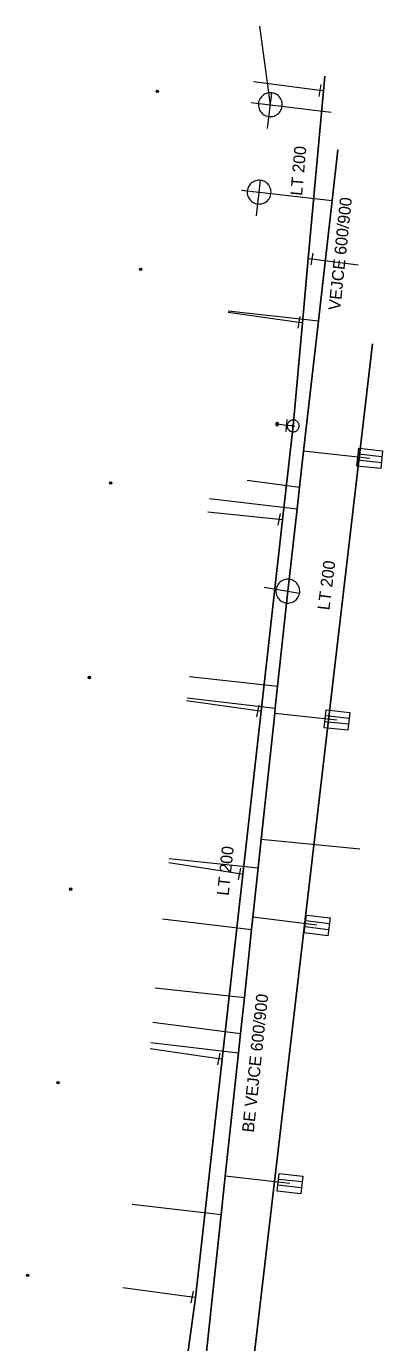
# Model space of a CAD drawing. Extents: x -783064 to -782702, y -1007904 to -1007145.
# Drawn here: x -782796 to -782766.2, y -1007400.8 to -1007290.3 of the extents above; entities that cross this region are included whole.
import ezdxf

# ---------------------------------------------------------------- set-up
doc = ezdxf.new("R2010")
doc.units = 0
doc.header["$LTSCALE"] = 0.4
doc.header["$PDMODE"] = 32
doc.header["$PDSIZE"] = 0.2
for name, color, linetype, lineweight in [('1', 7, 'Continuous', 13), ('11', 7, 'Continuous', 13), ('13', 7, 'Continuous', 13), ('14', 7, 'Continuous', 13), ('17', 7, 'Continuous', 25), ('22', 7, 'Continuous', 13), ('34', 7, 'Continuous', 13), ('47', 7, 'Continuous', 13), ('9', 7, 'Continuous', 13)]:
    doc.layers.add(name, color=color, linetype=linetype, lineweight=lineweight)

msp = doc.modelspace()

# ---------------------------------------------------------------- linework, layer by layer
at = {"layer": '1'}
for p in [(-782785.07, -1007295.79), (-782786.46, -1007310.729), (-782788.969, -1007328.649), (-782790.76, -1007344.969), (-782792.32, -1007362.729), (-782793.39, -1007378.959), (-782795.94, -1007395.139)]:
    msp.add_point(p, dxfattribs=at)
at = {"layer": '11'}
for p, q in [((-782776.496, -1007290.33), (-782775.599, -1007296.909)), ((-782777.204, -1007296.714), (-782775.599, -1007296.909)), ((-782775.599, -1007296.909), (-782770.506, -1007297.528)), ((-782778.017, -1007304.068), (-782776.537, -1007304.241)), ((-782776.537, -1007304.241), (-782770.429, -1007304.956)), ((-782779.125, -1007314.215), (-782771.569, -1007315.044)), ((-782767.274, -1007326.579), (-782772.805, -1007325.976)), ((-782777.54, -1007328.416), (-782773.146, -1007328.99)), ((-782780.703, -1007329.958), (-782773.35, -1007330.802)), ((-782782.381, -1007344.886), (-782774.984, -1007345.702)), ((-782782.58, -1007346.681), (-782775.18, -1007347.535)), ((-782770.021, -1007348.535), (-782775.227, -1007347.977)), ((-782768.104, -1007359.371), (-782776.357, -1007358.573)), ((-782784.073, -1007360.146), (-782776.611, -1007360.948)), ((-782771.688, -1007365.759), (-782777.052, -1007365.088)), ((-782784.626, -1007365.221), (-782777.162, -1007366.117)), ((-782785.256, -1007371.004), (-782777.771, -1007371.826)), ((-782785.437, -1007373.877), (-782778.092, -1007374.836)), ((-782785.601, -1007375.589), (-782778.267, -1007376.47)), ((-782773.95, -1007387.429), (-782779.371, -1007386.822)), ((-782787.188, -1007389.165), (-782779.714, -1007390.038))]:
    msp.add_line(p, q, dxfattribs=at)
at = {"layer": '13'}
for p, q in [((-782771.453, -1007295.717), (-782777.014, -1007294.994)), ((-782772.123, -1007309.847), (-782768.225, -1007310.354)), ((-782773.205, -1007315.178), (-782779.139, -1007314.338)), ((-782774.865, -1007331.708), (-782780.827, -1007331.085)), ((-782776.662, -1007347.776), (-782782.629, -1007346.914)), ((-782778.192, -1007361.449), (-782784.114, -1007360.525)), ((-782779.928, -1007376.969), (-782785.661, -1007376.137)), ((-782782.164, -1007396.953), (-782787.97, -1007396.189))]:
    msp.add_line(p, q, dxfattribs=at)
at = {"layer": '14'}
for p, q in [((-782771.154, -1007295.742), (-782771.453, -1007295.717)), ((-782772.421, -1007309.814), (-782772.123, -1007309.847)), ((-782772.907, -1007315.211), (-782773.205, -1007315.178)), ((-782774.256, -1007323.821), (-782775.023, -1007323.703)), ((-782773.685, -1007323.861), (-782774.256, -1007323.821)), ((-782774.568, -1007331.749), (-782774.865, -1007331.708)), ((-782776.364, -1007347.807), (-782776.662, -1007347.776)), ((-782777.895, -1007361.492), (-782778.192, -1007361.449)), ((-782779.629, -1007376.989), (-782779.928, -1007376.969)), ((-782781.868, -1007397.002), (-782782.164, -1007396.953))]:
    msp.add_line(p, q, dxfattribs=at)
at = {"layer": '14', "lineweight": 25}
for points in [[(-782774.133, -1007337.723), (-782773.35, -1007330.802), (-782773.146, -1007328.99), (-782772.805, -1007325.976), (-782771.569, -1007315.044), (-782770.429, -1007304.956), (-782769.945, -1007300.681)], [(-782782.09, -1007412.3), (-782779.714, -1007390.038), (-782779.371, -1007386.822), (-782778.267, -1007376.47), (-782778.092, -1007374.836), (-782777.771, -1007371.826), (-782777.162, -1007366.117), (-782777.052, -1007365.088), (-782776.611, -1007360.948), (-782776.357, -1007358.573), (-782775.227, -1007347.977), (-782775.18, -1007347.535), (-782774.984, -1007345.702), (-782774.133, -1007337.723)]]:
    msp.add_lwpolyline(points, dxfattribs=at)
at = {"layer": '17'}
msp.add_line((-782777.911, -1007410.054), (-782767.049, -1007316.969), dxfattribs=at)
for points in [[(-782773.685, -1007323.861), (-782772.907, -1007315.211), (-782772.421, -1007309.814), (-782771.154, -1007295.742), (-782771.043, -1007294.509)], [(-782782.979, -1007405.1), (-782781.87, -1007397.02), (-782779.629, -1007376.989), (-782777.895, -1007361.492), (-782776.364, -1007347.807), (-782774.568, -1007331.749), (-782773.685, -1007323.861)]]:
    msp.add_lwpolyline(points, dxfattribs=at)
at = {"layer": '22'}
for p, q in [((-782775.84, -1007298.894), (-782775.478, -1007295.916)), ((-782776.769, -1007306.227), (-782776.42, -1007303.248)), ((-782766.242, -1007326.446), (-782768.23, -1007326.229)), ((-782766.296, -1007326.943), (-782768.284, -1007326.726)), ((-782776.103, -1007337.375), (-782773.148, -1007337.896)), ((-782768.989, -1007348.4), (-782770.978, -1007348.187)), ((-782769.043, -1007348.897), (-782771.031, -1007348.684)), ((-782770.716, -1007366.139), (-782772.701, -1007365.89)), ((-782770.654, -1007365.642), (-782772.639, -1007365.394)), ((-782772.918, -1007387.299), (-782774.905, -1007387.077)), ((-782772.973, -1007387.796), (-782774.961, -1007387.573))]:
    msp.add_line(p, q, dxfattribs=at)
for points in [[(-782774.606, -1007297.03), (-782774.599, -1007296.921), (-782774.604, -1007296.811), (-782774.62, -1007296.703), (-782774.648, -1007296.597), (-782774.688, -1007296.495), (-782774.739, -1007296.398), (-782774.8, -1007296.307), (-782774.871, -1007296.224), (-782774.95, -1007296.148), (-782775.037, -1007296.082), (-782775.13, -1007296.025), (-782775.231, -1007295.98), (-782775.334, -1007295.945), (-782775.441, -1007295.922), (-782775.551, -1007295.91), (-782775.66, -1007295.911), (-782775.769, -1007295.923), (-782775.876, -1007295.948), (-782775.979, -1007295.984), (-782776.077, -1007296.031), (-782776.171, -1007296.089), (-782776.257, -1007296.156), (-782776.335, -1007296.233), (-782776.405, -1007296.317), (-782776.465, -1007296.409), (-782776.514, -1007296.507), (-782776.552, -1007296.61), (-782776.579, -1007296.715), (-782776.595, -1007296.824), (-782776.598, -1007296.934), (-782776.59, -1007297.042), (-782776.569, -1007297.15), (-782776.537, -1007297.254), (-782776.494, -1007297.355), (-782776.439, -1007297.451), (-782776.375, -1007297.539), (-782776.302, -1007297.62), (-782776.22, -1007297.693), (-782776.131, -1007297.756), (-782776.034, -1007297.809), (-782775.934, -1007297.851), (-782775.829, -1007297.882), (-782775.72, -1007297.902), (-782775.611, -1007297.909), (-782775.502, -1007297.904), (-782775.394, -1007297.888), (-782775.288, -1007297.859), (-782775.185, -1007297.82), (-782775.089, -1007297.769), (-782774.998, -1007297.708), (-782774.914, -1007297.638), (-782774.838, -1007297.558), (-782774.771, -1007297.472), (-782774.716, -1007297.378), (-782774.669, -1007297.279), (-782774.635, -1007297.174), (-782774.611, -1007297.067)], [(-782775.543, -1007304.357), (-782775.537, -1007304.248), (-782775.542, -1007304.139), (-782775.559, -1007304.03), (-782775.587, -1007303.925), (-782775.628, -1007303.823), (-782775.679, -1007303.726), (-782775.741, -1007303.635), (-782775.812, -1007303.553), (-782775.891, -1007303.477), (-782775.978, -1007303.411), (-782776.072, -1007303.355), (-782776.173, -1007303.31), (-782776.277, -1007303.276), (-782776.384, -1007303.253), (-782776.493, -1007303.242), (-782776.602, -1007303.244), (-782776.711, -1007303.256), (-782776.818, -1007303.281), (-782776.921, -1007303.318), (-782777.019, -1007303.365), (-782777.112, -1007303.423), (-782777.198, -1007303.491), (-782777.276, -1007303.568), (-782777.346, -1007303.653), (-782777.405, -1007303.745), (-782777.453, -1007303.843), (-782777.492, -1007303.946), (-782777.518, -1007304.052), (-782777.533, -1007304.161), (-782777.536, -1007304.27), (-782777.527, -1007304.379), (-782777.506, -1007304.486), (-782777.474, -1007304.59), (-782777.43, -1007304.691), (-782777.375, -1007304.786), (-782777.31, -1007304.874), (-782777.236, -1007304.955), (-782777.154, -1007305.028), (-782777.065, -1007305.09), (-782776.968, -1007305.143), (-782776.868, -1007305.185), (-782776.762, -1007305.215), (-782776.654, -1007305.234), (-782776.545, -1007305.241), (-782776.436, -1007305.235), (-782776.328, -1007305.219), (-782776.222, -1007305.19), (-782776.119, -1007305.15), (-782776.023, -1007305.099), (-782775.932, -1007305.038), (-782775.848, -1007304.967), (-782775.774, -1007304.887), (-782775.707, -1007304.8), (-782775.652, -1007304.706), (-782775.606, -1007304.607), (-782775.571, -1007304.502), (-782775.549, -1007304.395)], [(-782766.35, -1007327.44), (-782768.339, -1007327.223), (-782768.176, -1007325.732), (-782766.188, -1007325.949)], [(-782774.307, -1007338.707), (-782774.198, -1007338.72), (-782774.089, -1007338.721), (-782773.979, -1007338.71), (-782773.873, -1007338.688), (-782773.768, -1007338.654), (-782773.669, -1007338.608), (-782773.575, -1007338.552), (-782773.488, -1007338.486), (-782773.408, -1007338.411), (-782773.337, -1007338.328), (-782773.275, -1007338.237), (-782773.225, -1007338.139), (-782773.184, -1007338.038), (-782773.156, -1007337.932), (-782773.138, -1007337.824), (-782773.133, -1007337.715), (-782773.14, -1007337.605), (-782773.158, -1007337.497), (-782773.189, -1007337.392), (-782773.23, -1007337.292), (-782773.283, -1007337.195), (-782773.346, -1007337.106), (-782773.419, -1007337.023), (-782773.499, -1007336.949), (-782773.587, -1007336.884), (-782773.682, -1007336.83), (-782773.783, -1007336.786), (-782773.887, -1007336.753), (-782773.995, -1007336.732), (-782774.104, -1007336.723), (-782774.213, -1007336.725), (-782774.321, -1007336.741), (-782774.428, -1007336.767), (-782774.531, -1007336.804), (-782774.629, -1007336.854), (-782774.72, -1007336.913), (-782774.806, -1007336.982), (-782774.882, -1007337.06), (-782774.95, -1007337.146), (-782775.008, -1007337.239), (-782775.056, -1007337.337), (-782775.093, -1007337.44), (-782775.118, -1007337.548), (-782775.131, -1007337.656), (-782775.132, -1007337.766), (-782775.121, -1007337.874), (-782775.099, -1007337.982), (-782775.064, -1007338.086), (-782775.019, -1007338.186), (-782774.963, -1007338.28), (-782774.898, -1007338.367), (-782774.822, -1007338.447), (-782774.739, -1007338.518), (-782774.649, -1007338.579), (-782774.552, -1007338.63), (-782774.449, -1007338.671), (-782774.344, -1007338.7)], [(-782769.096, -1007349.394), (-782771.084, -1007349.181), (-782770.925, -1007347.69), (-782768.936, -1007347.903)], [(-782770.778, -1007366.635), (-782772.763, -1007366.386), (-782772.577, -1007364.898), (-782770.592, -1007365.146)], [(-782773.029, -1007388.293), (-782775.016, -1007388.07), (-782774.85, -1007386.58), (-782772.862, -1007386.802)]]:
    msp.add_lwpolyline(points, close=True, dxfattribs=at)
at = {"layer": '34'}
for p, q in [((-782771.361, -1007295.225), (-782771.545, -1007296.208)), ((-782772.031, -1007309.355), (-782772.215, -1007310.338)), ((-782773.113, -1007314.686), (-782773.297, -1007315.669)), ((-782774.203, -1007323.323), (-782774.309, -1007324.318)), ((-782774.773, -1007331.216), (-782774.957, -1007332.199)), ((-782776.57, -1007347.284), (-782776.754, -1007348.267)), ((-782778.1, -1007360.957), (-782778.284, -1007361.94)), ((-782779.836, -1007376.477), (-782780.02, -1007377.46)), ((-782782.072, -1007396.461), (-782782.256, -1007397.444))]:
    msp.add_line(p, q, dxfattribs=at)
at = {"layer": '47'}
for points in [[(-782773.62, -1007323.365), (-782773.672, -1007323.361), (-782773.725, -1007323.362), (-782773.776, -1007323.37), (-782773.827, -1007323.381), (-782773.877, -1007323.399), (-782773.924, -1007323.422), (-782773.968, -1007323.45), (-782774.01, -1007323.482), (-782774.047, -1007323.517), (-782774.082, -1007323.557), (-782774.112, -1007323.6), (-782774.136, -1007323.647), (-782774.156, -1007323.695), (-782774.171, -1007323.745), (-782774.18, -1007323.796), (-782774.184, -1007323.848), (-782774.183, -1007323.901), (-782774.175, -1007323.953), (-782774.164, -1007324.003), (-782774.146, -1007324.053), (-782774.123, -1007324.1), (-782774.095, -1007324.145), (-782774.064, -1007324.186), (-782774.028, -1007324.224), (-782773.988, -1007324.258), (-782773.945, -1007324.288), (-782773.898, -1007324.313), (-782773.85, -1007324.332), (-782773.8, -1007324.347), (-782773.749, -1007324.356), (-782773.697, -1007324.36), (-782773.644, -1007324.359), (-782773.592, -1007324.352), (-782773.542, -1007324.34), (-782773.492, -1007324.322), (-782773.445, -1007324.3), (-782773.4, -1007324.272), (-782773.359, -1007324.241), (-782773.321, -1007324.204), (-782773.287, -1007324.164), (-782773.257, -1007324.121), (-782773.232, -1007324.075), (-782773.213, -1007324.026), (-782773.198, -1007323.976), (-782773.189, -1007323.925), (-782773.185, -1007323.873), (-782773.186, -1007323.82), (-782773.193, -1007323.769), (-782773.205, -1007323.718), (-782773.223, -1007323.668), (-782773.245, -1007323.621), (-782773.273, -1007323.577), (-782773.305, -1007323.536), (-782773.341, -1007323.498), (-782773.381, -1007323.463), (-782773.424, -1007323.433), (-782773.47, -1007323.409), (-782773.519, -1007323.389), (-782773.569, -1007323.374)], [(-782773.674, -1007323.779), (-782773.683, -1007323.778), (-782773.691, -1007323.779), (-782773.699, -1007323.78), (-782773.708, -1007323.782), (-782773.716, -1007323.785), (-782773.724, -1007323.789), (-782773.731, -1007323.793), (-782773.738, -1007323.798), (-782773.744, -1007323.804), (-782773.75, -1007323.811), (-782773.755, -1007323.818), (-782773.759, -1007323.826), (-782773.762, -1007323.833), (-782773.765, -1007323.841), (-782773.766, -1007323.85), (-782773.767, -1007323.859), (-782773.766, -1007323.867), (-782773.765, -1007323.875), (-782773.763, -1007323.884), (-782773.76, -1007323.892), (-782773.756, -1007323.9), (-782773.752, -1007323.907), (-782773.747, -1007323.914), (-782773.741, -1007323.921), (-782773.734, -1007323.926), (-782773.727, -1007323.931), (-782773.719, -1007323.935), (-782773.712, -1007323.938), (-782773.704, -1007323.941), (-782773.695, -1007323.942), (-782773.686, -1007323.943), (-782773.678, -1007323.942), (-782773.67, -1007323.941), (-782773.661, -1007323.939), (-782773.653, -1007323.936), (-782773.646, -1007323.933), (-782773.638, -1007323.928), (-782773.631, -1007323.923), (-782773.624, -1007323.917), (-782773.619, -1007323.91), (-782773.614, -1007323.903), (-782773.61, -1007323.895), (-782773.607, -1007323.888), (-782773.604, -1007323.88), (-782773.603, -1007323.871), (-782773.602, -1007323.862), (-782773.603, -1007323.854), (-782773.604, -1007323.846), (-782773.606, -1007323.837), (-782773.609, -1007323.829), (-782773.612, -1007323.822), (-782773.617, -1007323.814), (-782773.622, -1007323.807), (-782773.628, -1007323.801), (-782773.635, -1007323.795), (-782773.642, -1007323.79), (-782773.65, -1007323.786), (-782773.657, -1007323.783), (-782773.665, -1007323.78)]]:
    msp.add_lwpolyline(points, close=True, dxfattribs=at)
at = {"layer": '9'}
for points in [[(-782775.149, -1007323.703), (-782775.149, -1007323.716), (-782775.147, -1007323.729), (-782775.144, -1007323.742), (-782775.139, -1007323.754), (-782775.133, -1007323.766), (-782775.126, -1007323.777), (-782775.118, -1007323.787), (-782775.108, -1007323.797), (-782775.098, -1007323.805), (-782775.087, -1007323.812), (-782775.075, -1007323.818), (-782775.063, -1007323.823), (-782775.05, -1007323.826), (-782775.037, -1007323.828), (-782775.024, -1007323.83), (-782775.011, -1007323.829), (-782774.998, -1007323.827), (-782774.985, -1007323.824), (-782774.973, -1007323.819), (-782774.961, -1007323.813), (-782774.95, -1007323.806), (-782774.94, -1007323.798), (-782774.93, -1007323.788), (-782774.922, -1007323.778), (-782774.915, -1007323.767), (-782774.909, -1007323.755), (-782774.904, -1007323.743), (-782774.901, -1007323.73), (-782774.899, -1007323.717), (-782774.897, -1007323.704), (-782774.898, -1007323.691), (-782774.9, -1007323.678), (-782774.903, -1007323.665), (-782774.908, -1007323.653), (-782774.914, -1007323.641), (-782774.921, -1007323.63), (-782774.929, -1007323.62), (-782774.939, -1007323.61), (-782774.949, -1007323.602), (-782774.96, -1007323.595), (-782774.972, -1007323.589), (-782774.984, -1007323.584), (-782774.997, -1007323.581), (-782775.01, -1007323.579), (-782775.023, -1007323.578), (-782775.036, -1007323.578), (-782775.049, -1007323.58), (-782775.062, -1007323.583), (-782775.074, -1007323.588), (-782775.086, -1007323.594), (-782775.097, -1007323.601), (-782775.107, -1007323.609), (-782775.117, -1007323.619), (-782775.125, -1007323.629), (-782775.132, -1007323.64), (-782775.138, -1007323.652), (-782775.143, -1007323.664), (-782775.146, -1007323.677), (-782775.148, -1007323.69)], [(-782775.129, -1007323.703), (-782775.13, -1007323.714), (-782775.128, -1007323.725), (-782775.125, -1007323.736), (-782775.121, -1007323.746), (-782775.116, -1007323.756), (-782775.11, -1007323.765), (-782775.103, -1007323.774), (-782775.095, -1007323.782), (-782775.086, -1007323.789), (-782775.077, -1007323.795), (-782775.067, -1007323.8), (-782775.057, -1007323.804), (-782775.046, -1007323.807), (-782775.035, -1007323.81), (-782775.024, -1007323.81), (-782775.013, -1007323.81), (-782775.002, -1007323.808), (-782774.991, -1007323.805), (-782774.981, -1007323.801), (-782774.971, -1007323.796), (-782774.962, -1007323.79), (-782774.953, -1007323.783), (-782774.945, -1007323.775), (-782774.938, -1007323.766), (-782774.932, -1007323.757), (-782774.927, -1007323.747), (-782774.923, -1007323.737), (-782774.92, -1007323.726), (-782774.918, -1007323.715), (-782774.917, -1007323.704), (-782774.917, -1007323.693), (-782774.919, -1007323.682), (-782774.922, -1007323.671), (-782774.926, -1007323.661), (-782774.931, -1007323.651), (-782774.937, -1007323.642), (-782774.944, -1007323.633), (-782774.952, -1007323.625), (-782774.961, -1007323.618), (-782774.97, -1007323.612), (-782774.98, -1007323.607), (-782774.99, -1007323.603), (-782775.001, -1007323.6), (-782775.012, -1007323.598), (-782775.023, -1007323.598), (-782775.034, -1007323.597), (-782775.045, -1007323.599), (-782775.056, -1007323.602), (-782775.066, -1007323.606), (-782775.076, -1007323.611), (-782775.085, -1007323.617), (-782775.094, -1007323.624), (-782775.102, -1007323.632), (-782775.109, -1007323.641), (-782775.115, -1007323.65), (-782775.12, -1007323.66), (-782775.124, -1007323.67), (-782775.127, -1007323.681), (-782775.129, -1007323.692)], [(-782775.11, -1007323.703), (-782775.11, -1007323.712), (-782775.109, -1007323.721), (-782775.106, -1007323.73), (-782775.103, -1007323.738), (-782775.099, -1007323.746), (-782775.094, -1007323.754), (-782775.088, -1007323.761), (-782775.082, -1007323.767), (-782775.075, -1007323.773), (-782775.067, -1007323.778), (-782775.059, -1007323.782), (-782775.051, -1007323.785), (-782775.042, -1007323.788), (-782775.033, -1007323.789), (-782775.024, -1007323.791), (-782775.015, -1007323.79), (-782775.006, -1007323.789), (-782774.997, -1007323.786), (-782774.989, -1007323.783), (-782774.981, -1007323.779), (-782774.973, -1007323.774), (-782774.966, -1007323.768), (-782774.96, -1007323.762), (-782774.954, -1007323.755), (-782774.949, -1007323.747), (-782774.945, -1007323.739), (-782774.942, -1007323.731), (-782774.939, -1007323.722), (-782774.938, -1007323.713), (-782774.936, -1007323.704), (-782774.937, -1007323.695), (-782774.938, -1007323.686), (-782774.941, -1007323.677), (-782774.944, -1007323.669), (-782774.948, -1007323.661), (-782774.953, -1007323.653), (-782774.959, -1007323.646), (-782774.965, -1007323.64), (-782774.972, -1007323.634), (-782774.98, -1007323.629), (-782774.988, -1007323.625), (-782774.996, -1007323.622), (-782775.005, -1007323.619), (-782775.014, -1007323.618), (-782775.023, -1007323.617), (-782775.032, -1007323.617), (-782775.041, -1007323.618), (-782775.05, -1007323.621), (-782775.058, -1007323.624), (-782775.066, -1007323.628), (-782775.074, -1007323.633), (-782775.081, -1007323.639), (-782775.087, -1007323.645), (-782775.093, -1007323.652), (-782775.098, -1007323.66), (-782775.102, -1007323.668), (-782775.105, -1007323.676), (-782775.108, -1007323.685), (-782775.109, -1007323.694)], [(-782775.09, -1007323.703), (-782775.09, -1007323.71), (-782775.089, -1007323.717), (-782775.088, -1007323.724), (-782775.085, -1007323.73), (-782775.082, -1007323.736), (-782775.078, -1007323.742), (-782775.074, -1007323.748), (-782775.069, -1007323.753), (-782775.063, -1007323.757), (-782775.057, -1007323.761), (-782775.051, -1007323.764), (-782775.045, -1007323.767), (-782775.038, -1007323.768), (-782775.031, -1007323.771), (-782775.024, -1007323.771), (-782775.017, -1007323.771), (-782775.01, -1007323.769), (-782775.003, -1007323.768), (-782774.997, -1007323.765), (-782774.99, -1007323.762), (-782774.985, -1007323.758), (-782774.979, -1007323.754), (-782774.974, -1007323.749), (-782774.97, -1007323.743), (-782774.966, -1007323.737), (-782774.963, -1007323.731), (-782774.96, -1007323.725), (-782774.958, -1007323.718), (-782774.957, -1007323.711), (-782774.956, -1007323.704), (-782774.956, -1007323.697), (-782774.957, -1007323.69), (-782774.959, -1007323.683), (-782774.962, -1007323.677), (-782774.965, -1007323.67), (-782774.969, -1007323.665), (-782774.973, -1007323.659), (-782774.978, -1007323.654), (-782774.984, -1007323.65), (-782774.989, -1007323.646), (-782774.996, -1007323.643), (-782775.002, -1007323.64), (-782775.009, -1007323.638), (-782775.016, -1007323.637), (-782775.023, -1007323.637), (-782775.03, -1007323.637), (-782775.037, -1007323.637), (-782775.044, -1007323.639), (-782775.05, -1007323.642), (-782775.056, -1007323.645), (-782775.062, -1007323.649), (-782775.068, -1007323.653), (-782775.073, -1007323.658), (-782775.077, -1007323.664), (-782775.081, -1007323.669), (-782775.084, -1007323.676), (-782775.087, -1007323.682), (-782775.088, -1007323.689), (-782775.09, -1007323.696)], [(-782775.07, -1007323.703), (-782775.07, -1007323.708), (-782775.07, -1007323.713), (-782775.069, -1007323.718), (-782775.067, -1007323.722), (-782775.065, -1007323.727), (-782775.062, -1007323.731), (-782775.059, -1007323.734), (-782775.055, -1007323.738), (-782775.052, -1007323.741), (-782775.048, -1007323.744), (-782775.043, -1007323.746), (-782775.039, -1007323.748), (-782775.034, -1007323.749), (-782775.029, -1007323.751), (-782775.024, -1007323.751), (-782775.019, -1007323.751), (-782775.014, -1007323.75), (-782775.009, -1007323.749), (-782775.005, -1007323.747), (-782775, -1007323.745), (-782774.996, -1007323.742), (-782774.992, -1007323.739), (-782774.989, -1007323.735), (-782774.986, -1007323.732), (-782774.983, -1007323.728), (-782774.981, -1007323.723), (-782774.979, -1007323.719), (-782774.978, -1007323.714), (-782774.977, -1007323.709), (-782774.976, -1007323.704), (-782774.976, -1007323.699), (-782774.977, -1007323.694), (-782774.978, -1007323.689), (-782774.98, -1007323.685), (-782774.982, -1007323.68), (-782774.985, -1007323.676), (-782774.988, -1007323.672), (-782774.991, -1007323.669), (-782774.995, -1007323.666), (-782774.999, -1007323.663), (-782775.004, -1007323.661), (-782775.008, -1007323.659), (-782775.013, -1007323.658), (-782775.018, -1007323.657), (-782775.023, -1007323.657), (-782775.028, -1007323.657), (-782775.033, -1007323.658), (-782775.038, -1007323.658), (-782775.042, -1007323.66), (-782775.047, -1007323.662), (-782775.051, -1007323.665), (-782775.054, -1007323.668), (-782775.058, -1007323.671), (-782775.061, -1007323.675), (-782775.064, -1007323.679), (-782775.066, -1007323.684), (-782775.068, -1007323.688), (-782775.069, -1007323.693), (-782775.07, -1007323.698)], [(-782775.05, -1007323.703), (-782775.05, -1007323.706), (-782775.051, -1007323.709), (-782775.05, -1007323.711), (-782775.049, -1007323.714), (-782775.048, -1007323.717), (-782775.046, -1007323.719), (-782775.044, -1007323.721), (-782775.042, -1007323.723), (-782775.04, -1007323.725), (-782775.038, -1007323.727), (-782775.035, -1007323.729), (-782775.032, -1007323.73), (-782775.03, -1007323.73), (-782775.027, -1007323.731), (-782775.024, -1007323.731), (-782775.021, -1007323.731), (-782775.018, -1007323.731), (-782775.015, -1007323.73), (-782775.013, -1007323.729), (-782775.01, -1007323.728), (-782775.008, -1007323.726), (-782775.005, -1007323.724), (-782775.003, -1007323.722), (-782775.002, -1007323.72), (-782775, -1007323.718), (-782774.999, -1007323.715), (-782774.997, -1007323.712), (-782774.997, -1007323.71), (-782774.996, -1007323.707), (-782774.995, -1007323.704), (-782774.996, -1007323.701), (-782774.996, -1007323.698), (-782774.997, -1007323.695), (-782774.998, -1007323.693), (-782774.999, -1007323.69), (-782775.001, -1007323.688), (-782775.002, -1007323.685), (-782775.004, -1007323.683), (-782775.007, -1007323.682), (-782775.009, -1007323.68), (-782775.012, -1007323.679), (-782775.014, -1007323.678), (-782775.017, -1007323.677), (-782775.02, -1007323.677), (-782775.023, -1007323.676), (-782775.026, -1007323.677), (-782775.029, -1007323.676), (-782775.031, -1007323.678), (-782775.034, -1007323.678), (-782775.037, -1007323.679), (-782775.039, -1007323.681), (-782775.041, -1007323.682), (-782775.043, -1007323.684), (-782775.045, -1007323.687), (-782775.047, -1007323.689), (-782775.048, -1007323.692), (-782775.049, -1007323.694), (-782775.05, -1007323.697), (-782775.05, -1007323.7)], [(-782775.031, -1007323.703), (-782775.031, -1007323.705), (-782775.031, -1007323.705), (-782775.03, -1007323.705), (-782775.03, -1007323.707), (-782775.031, -1007323.708), (-782775.029, -1007323.708), (-782775.029, -1007323.708), (-782775.029, -1007323.71), (-782775.029, -1007323.71), (-782775.028, -1007323.711), (-782775.026, -1007323.711), (-782775.026, -1007323.711), (-782775.026, -1007323.712), (-782775.024, -1007323.712), (-782775.024, -1007323.712), (-782775.023, -1007323.712), (-782775.022, -1007323.712), (-782775.022, -1007323.711), (-782775.021, -1007323.711), (-782775.019, -1007323.711), (-782775.019, -1007323.71), (-782775.019, -1007323.71), (-782775.018, -1007323.709), (-782775.018, -1007323.709), (-782775.016, -1007323.708), (-782775.016, -1007323.707), (-782775.015, -1007323.706), (-782775.015, -1007323.706), (-782775.015, -1007323.705), (-782775.015, -1007323.704), (-782775.015, -1007323.703), (-782775.015, -1007323.702), (-782775.015, -1007323.702), (-782775.016, -1007323.701), (-782775.016, -1007323.7), (-782775.017, -1007323.699), (-782775.017, -1007323.699), (-782775.018, -1007323.698), (-782775.018, -1007323.698), (-782775.019, -1007323.697), (-782775.02, -1007323.697), (-782775.021, -1007323.696), (-782775.021, -1007323.696), (-782775.022, -1007323.696), (-782775.023, -1007323.696), (-782775.024, -1007323.696), (-782775.025, -1007323.696), (-782775.025, -1007323.696), (-782775.026, -1007323.697), (-782775.027, -1007323.696), (-782775.028, -1007323.698), (-782775.028, -1007323.698), (-782775.029, -1007323.698), (-782775.029, -1007323.698), (-782775.03, -1007323.7), (-782775.03, -1007323.701), (-782775.03, -1007323.702), (-782775.031, -1007323.702), (-782775.031, -1007323.703)]]:
    msp.add_lwpolyline(points, close=True, dxfattribs=at)

# ---------------------------------------------------------------- texts
at = {"layer": '1'}
for s, rotation, p in [('LT 200', 85, (-782772.937, -1007304.57)), ('  VEJCE 600/900 ', 84, (-782769.821, -1007314.935)), ('LT 200', 83, (-782770.653, -1007339.356)), ('LT 200', 84, (-782779.089, -1007363.311)), ('BE VEJCE 600/900', 84, (-782776.985, -1007383.176))]:
    msp.add_text(s, height=1, rotation=rotation, dxfattribs=at).set_placement(p)

doc.saveas('drawing.dxf')
